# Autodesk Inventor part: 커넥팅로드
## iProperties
Manager: KYOUNG IL JANG
Company: 한국ATC센터
Created: 2012-10
Part Number: 커넥팅로드
Document SubType Name: Modeling
Density: 1 g/cm^3
Checked By: KYOUNG IL JANG
Vendor: CBT Solutions
Designer: KYOUNG IL JANG
Author: KYOUNG IL JANG
